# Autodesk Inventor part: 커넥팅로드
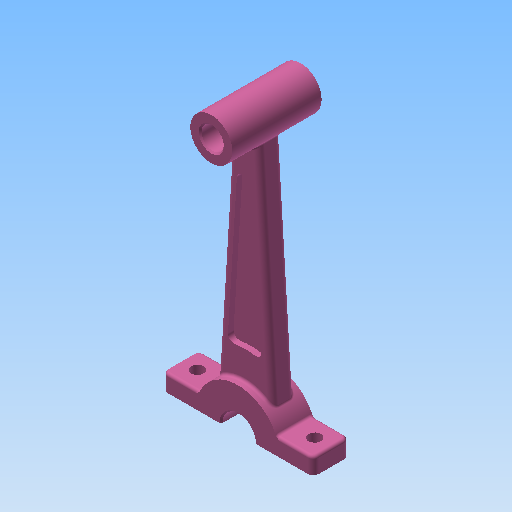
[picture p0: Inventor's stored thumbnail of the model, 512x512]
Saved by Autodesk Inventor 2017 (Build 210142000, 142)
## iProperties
Created: 2016-11
Part Number: 커넥팅로드
Material: 알루미늄 6061
Document SubType Name: Modeling
Designer: mduedu
Density: 2.71 g/cm^3
Mass: 44.549 g
Surface Area: 86.7069 cm^2
Volume: 16.4387 cm^3
Appearance: 분홍색
Author: mduedu
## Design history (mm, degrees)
sketch "스케치1" dims "d0" = 30, "d3" = 15
  geometry: L1 (0, 0)-(0, 96); L2 (-5, 90.41)-(-10, 11.18); L3 (5, 90.41)-(10, 11.18); C1 r 6 at (0, 0); C2 r 4 at (0, 96); 3 further points
  constraints: 6 end point, 4 coincident, 2 centre point, 2 symmetric about line, 1 vertical, 6 other
  dimensions: "d1" = 12 diameter of C1; "d2" = 8 diameter of C2; "d4" = 96 distance of L1.start L1.end; "d6" = 10 distance from line of L1 L2.end; "d7" = 5 distance from line of L1 L2.start
extrude "돌출1" new body sketch "스케치1" stored distance "d8" = 13; taper "d9" = 0 deg
extrude "돌출2" join sketch "스케치1" stored distance "d10" = 32; taper "d11" = 0 deg
sketch "스케치2"
  geometry: L1 (5, 90.41)-(10, 11.18) reference; L2 (-5, 90.41)-(-10, 11.18) reference; A1 r 7.5 centre (0, 96) between (5, 90.41) and (-5, 90.41) reference; A2 r 15 centre (0, 0) between (10, 11.18) and (-10, 11.18) reference
extrude "돌출3" join sketch "스케치2" stored distance "d12" = 8; taper "d13" = 0 deg
sketch "스케치3"
  geometry: L1 (-2.732, 78.715)-(-6.171, 24.226); L2 (2.732, 78.715)-(6.171, 24.226); L3 (0, 78.5)-(0, 25); A1 r 17.5 centre (0, 96) between (-2.732, 78.715) and (2.732, 78.715); A2 r 25 centre (0, 0) between (6.171, 24.226) and (-6.171, 24.226); 9 further points; 2 other entities
  constraints: 6 end point, 6 point on circle, 2 centre point, 1 symmetric about line, 1 vertical alignment, 6 other
  dimensions: "d18" = 10 dimension on A1; "d19" = 10 dimension on A2; "d20" = 3 dimension on L1
extrude "돌출4" cut sketch "스케치3" distance "d21" = 2; taper "d22" = 0 deg
fillet "모깎기1" dims "d23" = 2
fillet "모깎기2" dims "d24" = 2
fillet "모깎기3" dims "d25" = 1
chamfer "모따기1" distance "d26" = 0.5; stored, may be unused: second distance "d27" = 2, angle "d28" = 45 deg
sketch "스케치4"
  geometry: L1 (-27, -6)-(-13.748, -6); L2 (27, -6)-(27, 6); L3 (27, 6)-(13.748, 6); L4 (-27, 6)-(-27, -6); L5 (-27, -6)-(27, 6); L6 (27, -6)-(-27, 6); L7 (-13.748, 6)-(-27, 6); L8 (13.748, 6)-(-13.748, 6); L9 (13.748, -6)-(27, -6); L10 (-13.748, -6)-(13.748, -6); A1 r 15 centre (0, 0) between (-13.748, 6) and (13.748, 6) reference; 1 further point
  constraints: 20 end point, 10 parallel, 4 point on circle, 3 horizontal, 3 perpendicular, 2 midpoint
  dimensions: "d29" = 54 distance of L1.start L2.start; "d31" = 12 distance of L2.start L2.end
extrude "돌출5" join sketch "스케치4" stored distance "d32" = 0; taper "d33" = 0 deg
fillet "모깎기4" dims "d34" = 2
fillet "모깎기5" dims "d35" = 1
fillet "모깎기6" dims "d36" = 1
sketch "스케치5"
  geometry: L1 (1, 0)-(1, 9) reference; L2 (-18.5, 20.5)-(-33.5, 20.5) reference; L3 (-33.5, -11.5)-(-18.5, -11.5) reference; L4 (-26, 20.5)-(-26, -11.5); 3 further points
  constraints: 2 end point, 2 midpoint, 1 horizontal alignment, 1 symmetric about line
  dimensions: "d37" = 6 distance from line of point (-5, 4.5) L1
feature "분할1"
sketch "스케치7"
  geometry: 2 further points
  constraints: 2 other
hole "구멍2" sketch "스케치7" at (-47, 4.5), (-5, 4.5) diameter "d45" = 4.5; stored, may be unused: countersink angle "d49" = 90 deg, drill point angle "d51" = 0 deg; dims "d46" = 6, "d47" = 4, "d48" = 2, "d50" = 8
node "솔리드1"
mirror "대칭1"
other parameters: "d16" = 4, "d17" = 4
